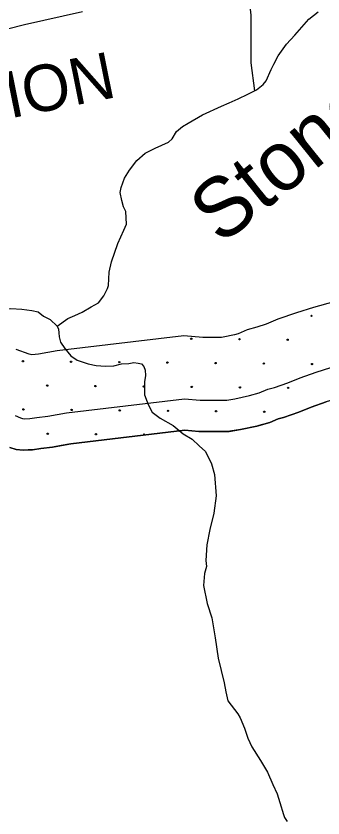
# Model space of a CAD drawing. Extents: x 1788175 to 1969470, y 584502 to 738744.
# Drawn here: x 1804355 to 1806805, y 674841 to 681239 of the extents above; entities that cross this region are included whole.
import ezdxf

# ---------------------------------------------------------------- set-up
doc = ezdxf.new("R2010")
doc.units = 0
for name, color, linetype in [('DESIGN - DRAINAGE - Bridges and Cross Drains Size Text', 7, 'Continuous'), ('DESIGN - EROSION CONTROL - Devices', 7, 'Continuous'), ('DESIGN - ROW - Right-of-Way and Easement Labels', 7, 'Continuous'), ('DESIGN - SCRATCH - User 1', 7, 'Continuous'), ('DESIGN - TRANSPORTATION - Text', 7, 'Continuous'), ('SURVEY - CONTOURS - Index with Text', 7, 'Continuous'), ('SURVEY - CONTOURS - Intermediate with optional Text', 7, 'Continuous'), ('SURVEY - VEGETATION - Features with Text', 7, 'Continuous')]:
    doc.layers.add(name, color=color, linetype=linetype)

msp = doc.modelspace()

# ---------------------------------------------------------------- linework, layer by layer
at = {"layer": 'DESIGN - EROSION CONTROL - Devices'}
for centre in [(1806713.5, 678847.4), (1805754, 678664.4), (1806138.6, 678660.7), (1806523.1, 678656.9), (1804410, 678485.2), (1804794.5, 678481.5), (1805179.1, 678477.7), (1805563.6, 678474), (1805948.2, 678470.3), (1806332.7, 678466.5), (1806717.3, 678462.8), (1804604.1, 678291.1), (1804988.7, 678287.3), (1805373.2, 678283.6), (1805757.8, 678279.9), (1806142.3, 678276.1), (1806526.9, 678272.4), (1804413.7, 678100.7), (1804798.3, 678096.9), (1805182.8, 678093.2), (1805567.4, 678089.5), (1805951.9, 678085.7), (1806336.5, 678082), (1804607.8, 677906.5), (1804992.4, 677902.8)]:
    msp.add_circle(centre, 5.28, dxfattribs=at)
msp.add_arc((1805376.9, 677899), 5.28, 316.00851, 237.62126, dxfattribs=at)
at = {"layer": 'DESIGN - SCRATCH - User 1'}
for points in [[(1806891.5, 678958.2), (1806728.1, 678914.3), (1806592.6, 678872.4), (1806444.3, 678819.4), (1806350.3, 678781.2), (1806276, 678756), (1806199.5, 678736.3), (1806127.4, 678704.2), (1806098.1, 678696.3), (1806008.7, 678676.7), (1805996.1, 678674.7), (1805847.1, 678673.5), (1805695.5, 678688.3), (1804684.4, 678567.5), (1804535.3, 678541.5), (1804481.1, 678534.8), (1804459.7, 678542.7), (1804355, 678577.8)], [(1804305.7, 677797.9), (1804356.6, 677781.8), (1804412.3, 677776.2), (1804485.9, 677779.2), (1804552.6, 677787.9), (1804646, 677799.5), (1804793.4, 677825.2), (1805703.5, 677933.9), (1805813.6, 677923.2), (1806057, 677925.2), (1806146.6, 677939.1), (1806277.2, 677967.7), (1806380, 677995.7), (1806447.3, 678025.7), (1806490, 678036.7), (1806611.9, 678077.9), (1806711.9, 678118.6), (1806829.8, 678160.7)]]:
    msp.add_lwpolyline(points, dxfattribs=at)
at = {"layer": 'DESIGN - TRANSPORTATION - Text'}
for points in [[(1805825.8, 683517.8), (1805782.5, 683362.5), (1805836.8, 683176), (1805877.5, 683076), (1805918.2, 682981), (1805931.7, 682845.4), (1805958.9, 682669.1), (1805999.6, 682492.7), (1806026.7, 682329.9), (1806080.9, 682112.9), (1806108.1, 681977.3), (1806135.2, 681814.5), (1806175.9, 681651.7), (1806203, 681488.9), (1806230.2, 681244.8), (1806230.2, 681054.9), (1806230.2, 680865), (1806259.6, 680642.7)], [(1804684.2, 678764), (1804768.3, 678825.9), (1804824.3, 678849.8), (1804882.3, 678877.7), (1804954.3, 678919.6), (1805014.4, 678951.5), (1805056.4, 679007.4), (1805084.5, 679065.3), (1805092.6, 679089.2), (1805098.7, 679195.1), (1805116.8, 679277), (1805167.1, 679424.8), (1805215.2, 679530.7), (1805237.3, 679578.6), (1805231.5, 679680.5), (1805213.5, 679716.5), (1805199.6, 679768.5), (1805185.7, 679832.4), (1805193.8, 679872.4), (1805219.9, 679946.3), (1805262, 680008.2), (1805318.1, 680086), (1805386.1, 680143.9), (1805466.2, 680185.7), (1805572.2, 680233.6), (1805600.2, 680259.5), (1805636.3, 680317.4), (1805684.4, 680357.3), (1805728.4, 680385.2), (1805844.4, 680451), (1805994.5, 680520.8), (1806056.5, 680546.7), (1806128.5, 680578.6), (1806204.5, 680614.5), (1806274.6, 680650.3), (1806326.6, 680692.2), (1806350.7, 680722.2), (1806390.8, 680812.1), (1806412.8, 680856), (1806446.9, 680921.9), (1806515.1, 681015.7), (1806581.1, 681085.6), (1806691.3, 681215.3), (1806767.4, 681273.2)], [(1802883.3, 678944), (1803145.1, 678911.7), (1803422.9, 678887.4), (1803502.9, 678877.3), (1803558.9, 678877.2), (1803626.9, 678885.2), (1803660.9, 678899.1), (1803718.9, 678913), (1803828.8, 678902.9), (1803914.7, 678890.8), (1804030.7, 678884.7), (1804084.7, 678884.6), (1804238.6, 678898.4), (1804312.6, 678906.3), (1804402.5, 678900.2), (1804480.5, 678890.2), (1804532.5, 678880.1), (1804574.4, 678844.1), (1804628.3, 678818.1), (1804684.2, 678764)], [(1804684.2, 678764), (1804694.2, 678742), (1804696.1, 678712.1), (1804698.1, 678680.1), (1804710, 678638.1), (1804743.9, 678586.1), (1804791.8, 678528.1), (1804843.7, 678494.1), (1804929.6, 678464), (1804993.6, 678452), (1805069.5, 678445.9), (1805135.5, 678447.8), (1805197.5, 678463.7), (1805255.5, 678467.7), (1805295.5, 678475.6), (1805329.5, 678469.6), (1805355.4, 678463.5), (1805375.4, 678443.5), (1805385.3, 678413.6), (1805387.3, 678371.6), (1805381.2, 678321.6), (1805379.1, 678271.7), (1805381, 678215.8), (1805408.9, 678139.8), (1805442.8, 678077.8), (1805504.7, 678031.8), (1805608.5, 677971.7), (1805688.4, 677905.7), (1805760.3, 677863.6), (1805816.2, 677809.6), (1805868.1, 677765.6), (1805913.9, 677665.7), (1805937.8, 677581.7), (1805951.5, 677411.9), (1805933.3, 677272), (1805901.1, 677142.2), (1805878.9, 677020.3), (1805870.7, 676894.5), (1805874.6, 676848.5), (1805860.5, 676790.6), (1805850.4, 676696.7), (1805880.1, 676552.8), (1805917.9, 676436.8), (1805945.6, 676279), (1805967.4, 676115.1), (1806015, 675919.2), (1806028.9, 675847.3), (1806046.8, 675775.3), (1806098.6, 675705.3), (1806124.6, 675671.3), (1806144.5, 675639.4), (1806178.4, 675557.4), (1806204.2, 675477.4), (1806238.1, 675407.5), (1806305.9, 675299.5), (1806361.7, 675207.5), (1806405.5, 675107.6), (1806439.4, 675033.6), (1806461.3, 674965.6), (1806491.1, 674867.7), (1806499.1, 674845.7), (1806519, 674813.7)]]:
    msp.add_lwpolyline(points, dxfattribs=at)
at = {"layer": 'SURVEY - CONTOURS - Index with Text'}
msp.add_lwpolyline([(1804885.9, 681271.5), (1804423.9, 681170.2), (1803991.9, 681058.9), (1803547.9, 680969.6), (1803193.8, 680876.2), (1802875.8, 680810.7), (1802569.8, 680733.2), (1802305.8, 680671.6), (1801971.8, 680588.2), (1801741.8, 680526.6), (1801585.7, 680482.8), (1801473.4, 680429.3), (1801351.6, 680355.3), (1801225.4, 680235.6), (1801021.1, 680008.2), (1800844.8, 679830.6), (1800726.6, 679696.9), (1800648.5, 679621.1), (1800552.4, 679555.4), (1800428.3, 679469.6), (1800316.2, 679423.8), (1800200.2, 679382), (1800102.2, 679342.2), (1799954.2, 679322.4)], dxfattribs=at)
at = {"layer": 'SURVEY - CONTOURS - Intermediate with optional Text'}
msp.add_lwpolyline([(1804347.2, 678051.1), (1804391.1, 678033.1), (1804407.4, 678027.9), (1804419.7, 678026.7), (1804464.6, 678028.5), (1804521.1, 678035.9), (1804609.1, 678046.8), (1804757.1, 678072.6), (1805700.8, 678185.4), (1805824.8, 678173.3), (1806036.7, 678175), (1806100.7, 678184.9), (1806217.5, 678210.6), (1806295.8, 678231.9), (1806364.7, 678262.6), (1806418.7, 678276.5), (1806524.7, 678312.3), (1806622.7, 678352.2), (1806750.7, 678398), (1806866.7, 678433.8)], dxfattribs=at)
at = {"layer": 'SURVEY - VEGETATION - Features with Text'}
for points in [[(1806829.8, 678160.7), (1806711.9, 678118.6), (1806611.9, 678077.9), (1806490, 678036.7), (1806447.3, 678025.7), (1806380, 677995.7), (1806277.2, 677967.7), (1806146.6, 677939.1), (1806057, 677925.2), (1805813.6, 677923.2), (1805703.5, 677933.9), (1804793.4, 677825.2), (1804646, 677799.5), (1804552.6, 677787.9), (1804485.9, 677779.2), (1804412.3, 677776.2), (1804356.6, 677781.8), (1804305.7, 677797.9)], [(1806960.5, 678200.1), (1806936, 678193.6), (1806829.8, 678160.7), (1806711.9, 678118.6), (1806709.8, 678117.7)], [(1806709.8, 678117.7), (1806611.9, 678077.9), (1806490, 678036.7), (1806461.3, 678029.3)], [(1806320.3, 677979.5), (1806277.2, 677967.7), (1806146.6, 677939.1), (1806062, 677926)], [(1805386.8, 677896.1), (1805124.7, 677864.8)], [(1805648.9, 677927.4), (1805386.8, 677896.1)], [(1806062, 677926), (1806057, 677925.2), (1805813.6, 677923.2), (1805798.1, 677924.7)], [(1804975.7, 677847), (1804793.4, 677825.2), (1804714.2, 677811.4)], [(1804714.2, 677811.4), (1804646, 677799.5), (1804552.6, 677787.9), (1804485.9, 677779.2), (1804452.6, 677777.8)]]:
    msp.add_lwpolyline(points, dxfattribs=at)

# ---------------------------------------------------------------- texts
at = {"layer": 'DESIGN - DRAINAGE - Bridges and Cross Drains Size Text'}
msp.add_text('Stoners', height=475, rotation=38.8339, dxfattribs=at).set_placement((1805990.5, 679404.9))
at = {"layer": 'DESIGN - ROW - Right-of-Way and Easement Labels'}
msp.add_text('DIVISION', height=370, rotation=11.37113, dxfattribs=at).set_placement((1803038.6, 680166.4))

doc.saveas('drawing.dxf')
